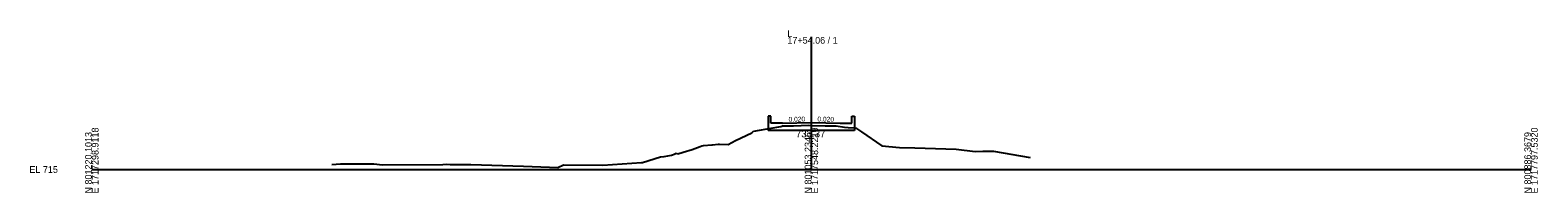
# Model space of a CAD drawing. Extents: x 974 to 5203, y -10 to 9544.
# Drawn here: x 4574 to 5203, y -10 to 58 of the extents above; entities that cross this region are included whole.
import ezdxf

# ---------------------------------------------------------------- set-up
doc = ezdxf.new("R2010")
doc.units = 0
for name, color, linetype in [('Exist Cross Section Cell', 7, 'Continuous'), ('Exist XS Center Line Elevation Label', 7, 'Continuous'), ('Exist XS Ground Line', 7, 'Continuous'), ('Prop XS Bridge', 7, 'Continuous'), ('Prop XS Dump Level', 7, 'Continuous'), ('Prop XS SE Text', 7, 'Continuous')]:
    doc.layers.add(name, color=color, linetype=linetype)

msp = doc.modelspace()

# ---------------------------------------------------------------- linework, layer by layer
at = {"layer": 'Exist Cross Section Cell'}
for p, q in [((4900, 0), (4900, 55.18)), ((4600, 0), (4900, 0)), ((4900, 0), (5200, 0))]:
    msp.add_line(p, q, dxfattribs=at)
at = {"layer": 'Exist XS Ground Line'}
for p, q in [((4868.41, 12.06), (4875.12, 15.27)), ((4875.12, 15.27), (4875.89, 16)), ((4875.89, 16), (4876.85, 16.15)), ((4876.85, 16.15), (4877.59, 16.25)), ((4877.59, 16.25), (4887.28, 17.92)), ((4887.28, 17.92), (4887.67, 17.98)), ((4887.67, 17.98), (4887.93, 18.11)), ((4887.93, 18.11), (4892.49, 18.23)), ((4892.49, 18.23), (4898.99, 18.39)), ((4898.99, 18.39), (4900, 18.37)), ((4900, 18.37), (4905.79, 18.23)), ((4905.79, 18.23), (4910.31, 18.13)), ((4910.31, 18.13), (4913.79, 17.64)), ((4913.79, 17.64), (4915.35, 17.51)), ((4915.35, 17.51), (4918.43, 17.28)), ((4918.43, 17.28), (4920.92, 15.69)), ((4920.92, 15.69), (4929.3, 9.87)), ((4841.67, 5.96), (4843.24, 6.51)), ((4843.24, 6.51), (4843.62, 6.75)), ((4843.62, 6.75), (4844.33, 6.53)), ((4844.33, 6.53), (4846.47, 7.24)), ((4846.47, 7.24), (4850.29, 8.31)), ((4850.29, 8.31), (4853.68, 9.64)), ((4853.68, 9.64), (4854.36, 9.89)), ((4854.36, 9.89), (4854.96, 10.04)), ((4854.96, 10.04), (4858.44, 10.23)), ((4858.44, 10.23), (4858.75, 10.32)), ((4858.75, 10.32), (4861.1, 10.52)), ((4861.1, 10.52), (4861.65, 10.54)), ((4861.65, 10.54), (4865.36, 10.4)), ((4865.36, 10.4), (4868.41, 12.06)), ((4929.3, 9.87), (4936.66, 9.19)), ((4936.66, 9.19), (4943.07, 9)), ((4943.07, 9), (4960.38, 8.44)), ((4960.38, 8.44), (4968.3, 7.53)), ((4968.3, 7.53), (4971.53, 7.65)), ((4971.53, 7.65), (4975.85, 7.64)), ((4975.85, 7.64), (4991.16, 4.94)), ((4700.13, 2.08), (4703.7, 2.41)), ((4703.7, 2.41), (4717.64, 2.31)), ((4717.64, 2.31), (4721.22, 1.95)), ((4721.22, 1.95), (4746.32, 2.08)), ((4746.32, 2.08), (4747.7, 2.28)), ((4747.7, 2.28), (4749.45, 2.05)), ((4749.45, 2.05), (4758.08, 2.1)), ((4758.08, 2.1), (4779.94, 1.42)), ((4779.94, 1.42), (4790.84, 0.99)), ((4790.84, 0.99), (4794.28, 0.88)), ((4794.28, 0.88), (4796.64, 1.93)), ((4796.64, 1.93), (4813.01, 1.75)), ((4813.01, 1.75), (4829.22, 2.86)), ((4829.22, 2.86), (4829.54, 2.89)), ((4829.54, 2.89), (4837.08, 5.28)), ((4837.08, 5.28), (4838.57, 5.44)), ((4838.57, 5.44), (4841.67, 5.96))]:
    msp.add_line(p, q, dxfattribs=at)
at = {"layer": 'Prop XS Bridge'}
for p, q in [((4882, 22.24), (4882, 19.24)), ((4883.08, 22.24), (4882, 22.24)), ((4882, 19.24), (4882, 16.27)), ((4883.08, 19.24), (4883.08, 22.24)), ((4888, 19.33), (4883.08, 19.24)), ((4888, 19.33), (4900, 19.57)), ((4900, 19.57), (4912, 19.33)), ((4912, 19.33), (4916.92, 19.24)), ((4916.92, 19.24), (4916.92, 22.24)), ((4916.92, 22.24), (4918, 22.24)), ((4918, 22.24), (4918, 19.24)), ((4918, 19.24), (4918, 16.27)), ((4918, 16.27), (4882, 16.27))]:
    msp.add_line(p, q, dxfattribs=at)
at = {"layer": 'Prop XS Dump Level'}
for p, q in [((4888, 19.33), (4900, 19.57)), ((4900, 19.57), (4912, 19.33))]:
    msp.add_line(p, q, dxfattribs=at)

# ---------------------------------------------------------------- texts
at = {"layer": 'Exist Cross Section Cell'}
for s, p in [('L', (4890, 55.18)), ('17+54.06 / 1', (4890, 52.38)), ('EL 715', (4574, -1.4))]:
    msp.add_text(s, height=2.8, dxfattribs=at).set_placement(p)
for s, p in [('N 801220.1013', (4600, -10)), ('E 1717298.9118', (4602.8, -10)), ('N 801053.2346', (4900, -10)), ('E 1717548.2219', (4902.8, -10)), ('N 800886.3679', (5200, -10)), ('E 1717797.5320', (5202.8, -10))]:
    msp.add_text(s, height=2.8, rotation=90, dxfattribs=at).set_placement(p)
at = {"layer": 'Exist XS Center Line Elevation Label'}
msp.add_text('733.37', height=3, dxfattribs=at).set_placement((4893.55, 13.37))
at = {"layer": 'Prop XS SE Text'}
for rotation, p in [(1.14576, (4890.49, 19.88)), (358.85424, (4902.49, 20.02))]:
    msp.add_text('0.020', height=2, rotation=rotation, dxfattribs=at).set_placement(p)

doc.saveas('drawing.dxf')
